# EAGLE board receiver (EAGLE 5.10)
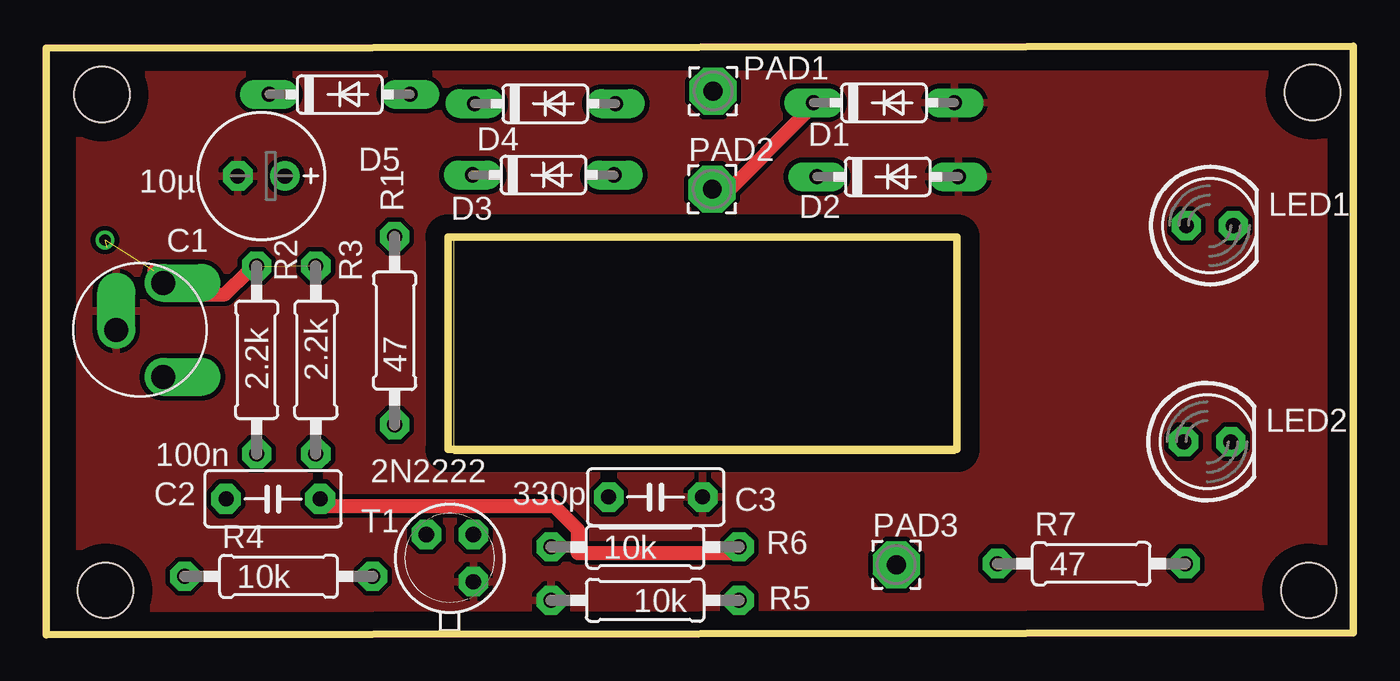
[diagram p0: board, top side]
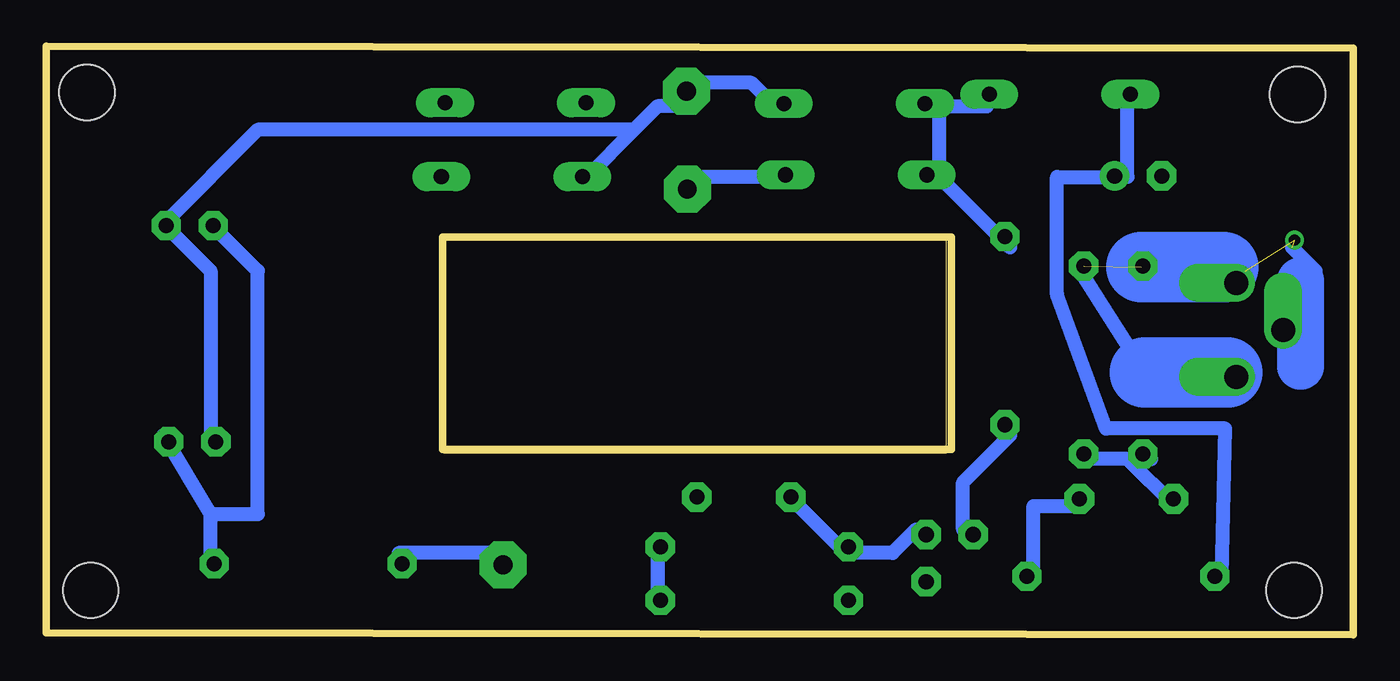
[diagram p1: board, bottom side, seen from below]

Size 70.6 x 31.8 mm. Coordinates in mm from the lower left corner, seen from the top.
Outline: 21.6,9.9 49.2,10
Outline: 49.2,21.6 21.6,21.6
Outline: 21.7,21.5 21.7,10 49.2,10
Outline: 49.1,21.5 21.8,21.5
Outline: 49.2,21.5 49.2,10
Outline: 0,31.7 70.6,31.8 70.6,0.1 0,0 0,31.7
Copper layers (1*16): Top 0.035mm / dielectric 1.5mm / Bottom 0.035mm
Design rules "default *": minimum track width 30mil, minimum drill 24mil, track to track 10mil, track to pad 10mil, pad to pad 8mil, via to via 8mil, smd to smd 8mil, copper to edge 40mil, drill to drill 10mil, minimum pad ring 15mil, minimum via ring 8mil, stop-mask expansion 4mil, vias tented up to drill 0mil, thermal gap 10mil
Holes 3 mm at 3,29.2 3.2,2.4 68.2,2.4 68.4,29.3
Milling: area 22,9.8 to 49.1,21.5

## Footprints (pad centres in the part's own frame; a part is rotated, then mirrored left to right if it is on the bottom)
E2,5-7 = drill 0.813 pad 1.6 round: + -1.27,0 | drill 0.813 pad 1.6 octagon: - 1.27,0
C5B3 = drill 0.813 pad 1.6 octagon: 1 -2.54,0; 2 2.54,0
DO35-7 = drill 0.813 long: A 3.81,0; C -3.81,0
LED5MM = drill 0.813 octagon: A -1.27,0; K 1.27,0
2,54/1,0 = drill 1.016 pad 2.54 octagon: 1 0,0
0207/10 = drill 0.813 octagon: 1 -5.08,0; 2 5.08,0
TO18 = drill 0.813 octagon: 1 -1.27,-1.27; 2 1.27,-1.27; 3 1.27,1.27
JACK_STEREO = drill 1.3 pad 1.778 offset: P$1 -5.08,3.81; P$2 -5.08,-1.27; P$3 -7.62,1.27

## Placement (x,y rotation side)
C1  10µ  [E2,5-7]  11.62,24.79 180 top
C2  100n  [C5B3]  12.25,7.34 180 top
C3  330p  [C5B3]  32.92,7.44 180 top
D1  1N5818  [DO35-7]  45.25,28.75 0 top
D2  1N5818  [DO35-7]  45.45,24.75 0 top
D3  1N5818  [DO35-7]  26.85,24.85 0 top
D4  1N5818  [DO35-7]  26.95,28.7 0 top
D5  1N5818  [DO35-7]  15.85,29.2 0 top
LED1  [LED5MM]  62.85,22.11 0 top
LED2  [LED5MM]  62.71,10.43 0 top
PAD1  [2,54/1,0]  36.02,29.38 0 top
PAD2  [2,54/1,0]  35.97,24.08 0 top
PAD3  [2,54/1,0]  45.92,3.78 0 top
R1  47  [0207/10]  18.82,16.43 90 top
R2  2.2k  [0207/10]  11.36,14.85 270 top
R3  2.2k  [0207/10]  14.56,14.85 270 top
R4  10k  [0207/10]  12.55,3.16 0 top
R5  10k  [0207/10]  32.35,1.86 180 top
R6  10k  [0207/10]  32.35,4.74 0 top
R7  47  [0207/10]  56.45,3.84 0 top
T1  2N2222  [TO18]  21.8,4.14 90 top
U$1  JACK_STEREO  [JACK_STEREO]  11.4,15.2 0 top

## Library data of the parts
C1-C3 D1-D5 PAD1-PAD3 R1-R7 T1 U$1 = PERSO_simple
LED1 LED2 = led

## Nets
+3VV: C1.+ D5.C R4.1
BLED: PAD3.1 R7.1
BOB1: D1.C D3.A PAD2.1
BOB2: D2.C D4.A LED1.K LED2.A PAD1.1
GND: C1.- C3.1 D1.A D2.A R5.2 T1.1 U$1.P$3
N$3: D3.C D4.C D5.A R1.2
N$4: R1.1 T1.3
N$8: C2.1 R4.2 R5.1 R6.2
N$9: C3.2 R6.1 T1.2
N$10: C2.2 R2.2 R3.2
N$11: LED1.A LED2.K R7.2
SOND: R2.1 U$1.P$1
SONG: R3.1 U$1.P$2

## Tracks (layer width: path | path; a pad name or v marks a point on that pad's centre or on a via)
+3VV
  Bottom 0.762: R4.1 7.11,3.15 6.91,11.14 13.35,11.14 16,18.39 16,24.74 13.46,24.74 C1.+ 12.19,24.74 12.19,28.55 D5.C
BLED
  Bottom 0.762: R7.1 51.56,4.42 46.48,4.42 PAD3.1
BOB1
  Top 0.762: D1.C 41.4,28.55 36.32,23.47 PAD2.1
  Bottom 0.762: D3.A 31.24,24.74 35.05,24.74 PAD2.1
BOB2
  Bottom 0.762: 64.26,22.2 61.72,19.66 61.72,10.77 LED2.A | D4.A 31.24,28.55 32.51,29.82 35.05,29.82 PAD1.1 36.32,28.55 37.59,28.55 38.86,27.28 | 38.86,27.28 41.4,24.74 D2.C | 64.26,22.2 59.18,27.28 38.86,27.28 | 64.26,22.2 LED1.K
GND
  pour Top: 1.8,30.3 69,30.3 69,13.5 69,0.8 1.8,0.8 1.8,30.2
N$3
  Bottom 0.762: 22.35,28.55 19.81,28.55 D5.A | 22.35,24.74 18.54,20.93 R1.2 | 22.35,24.74 22.35,28.55 | 22.35,28.55 D4.C | 22.35,24.74 D3.C
N$4
  Bottom 0.762: T1.3 21.08,5.69 21.08,8.23 18.54,10.77 R1.1
N$8
  Top 0.762: R6.2 37.59,4.42 28.7,4.42 28.7,5.69 27.43,6.96 14.73,6.96 C2.1
  Bottom 0.762: R5.1 37.59,1.88 37.59,4.42 R6.2 | R4.2 17.27,3.15 17.27,6.96 14.73,6.96 C2.1
N$9
  Bottom 0.762: 27.43,4.42 24.89,4.42 23.62,5.69 T1.2 | 27.43,4.42 29.97,6.96 C3.2 | 27.43,4.42 R6.1
N$10
  Bottom 0.762: 12.19,9.5 14.73,9.5 R3.2 | 12.19,9.5 10.92,9.5 R2.2 | 12.19,9.5 9.65,6.96 C2.2
N$11
  Bottom 0.762: 61.72,6.53 61.72,4.42 R7.2 | 61.72,6.53 64.26,10.77 LED2.K | 61.72,6.53 59.18,6.53 59.18,19.66 61.72,22.2 LED1.A
SOND  (via drill 0.61)  (2 unrouted)
  Top 0.762: 5.84,19.66 U$1.P$1 7.11,18.39 9.65,18.39 10.92,19.66 R2.1
  Bottom 0.762: R2.1 10.92,19.26 | 3,17.53 2.33,19.36 2.84,19.12 2.03,19.66 3.3,20.93
  Bottom 2.54: 10.92,19.26 6.71,19.26 | 2.84,14.51 2.84,19.12
  other vias: 3.17,21.33
SONG  (1 unrouted)
  Bottom 0.762: 11.25,14.18 14.73,19.66 R3.1 | U$1.P$2 6.81,14.18
  Bottom 3.81: 6.81,14.18 11.25,14.18 | 7.01,19.88 11.45,19.88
